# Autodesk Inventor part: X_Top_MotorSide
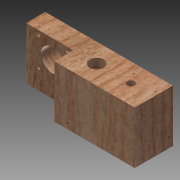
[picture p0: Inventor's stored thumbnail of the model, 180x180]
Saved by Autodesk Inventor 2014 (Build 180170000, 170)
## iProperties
Created: 2013-12
Part Number: X_Top_MotorSide
Material: Birch
Document SubType Name: Modeling
Designer: Bram
Density: 0.512 g/cm^3
Appearance: Birch - Natural Medium Gloss
Author: Bram
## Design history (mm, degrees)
sketch "Sketch1"
  geometry: L1 (0, 0)-(134, 0); L2 (134, 0)-(134, 40); L3 (134, 40)-(0, 40); L4 (0, 40)-(0, 0)
  constraints: 8 end point, 2 parallel, 1 horizontal, 1 perpendicular
  dimensions: "d0" = 134 distance of L3.end L2.end; "d1" = 40 distance of L2.end L1.end
extrude "Extrusion1" new body sketch "Sketch1" distance "d2" = 55; taper "d3" = 0 deg
sketch "Sketch2"
  geometry: L1 (0, 0)-(134, 0) reference; L2 (0, 40)-(0, 0) reference; L3 (0, 20)-(49.5, 20); L4 (49.5, 20)-(49.5, 0)
  constraints: 4 end point, 2 perpendicular, 1 midpoint, 1 point on line
  dimensions: "d4" = 49.5 distance of L3.start L3.end
extrude "Extrusion2" cut sketch "Sketch2" distance "d5" = 55; taper "d6" = 0 deg
sketch "Sketch3"
  geometry: L1 (134, 0)-(134, 40) reference; L2 (0, 20)-(49.5, 20) reference; L3 (134, 20)-(110, 20); L4 (110, 20)-(74, 20); C1 r 7.5 at (74, 20); C2 r 4 at (110, 20); 1 further point
  constraints: 4 end point, 2 centre point, 2 coincident, 2 collinear, 1 midpoint
  dimensions: "d7" = 24 distance of L3.start L3.end; "d8" = 36 distance of L3.end L4.end; "d9" = 15 diameter of C1; "d10" = 8 diameter of C2
extrude "Extrusion3" cut sketch "Sketch3" distance "d11" = 55; taper "d12" = 0 deg
sketch "Sketch4"
  geometry: L1 (27.5, -20)-(43, -20); C1 r 12 at (27.5, -20); C2 r 1.5 at (13, -4.5); C3 r 1.5 at (43, -4.5); C4 r 1.5 at (43, -34.5); C5 r 1.5 at (13, -34.5)
  constraints: 5 centre point, 2 end point
  dimensions: "d15" = 24 diameter of C1; "d16" = 15.5 distance of L1.start L1.end; "d21" = 3 diameter of C2; "d22" = 3 diameter of C3; "d23" = 3 diameter of C4; "d24" = 3 diameter of C5
extrude "Extrusion4" cut sketch "Sketch4" distance "d25" = 55; taper "d26" = 0 deg
body "Solid1"
